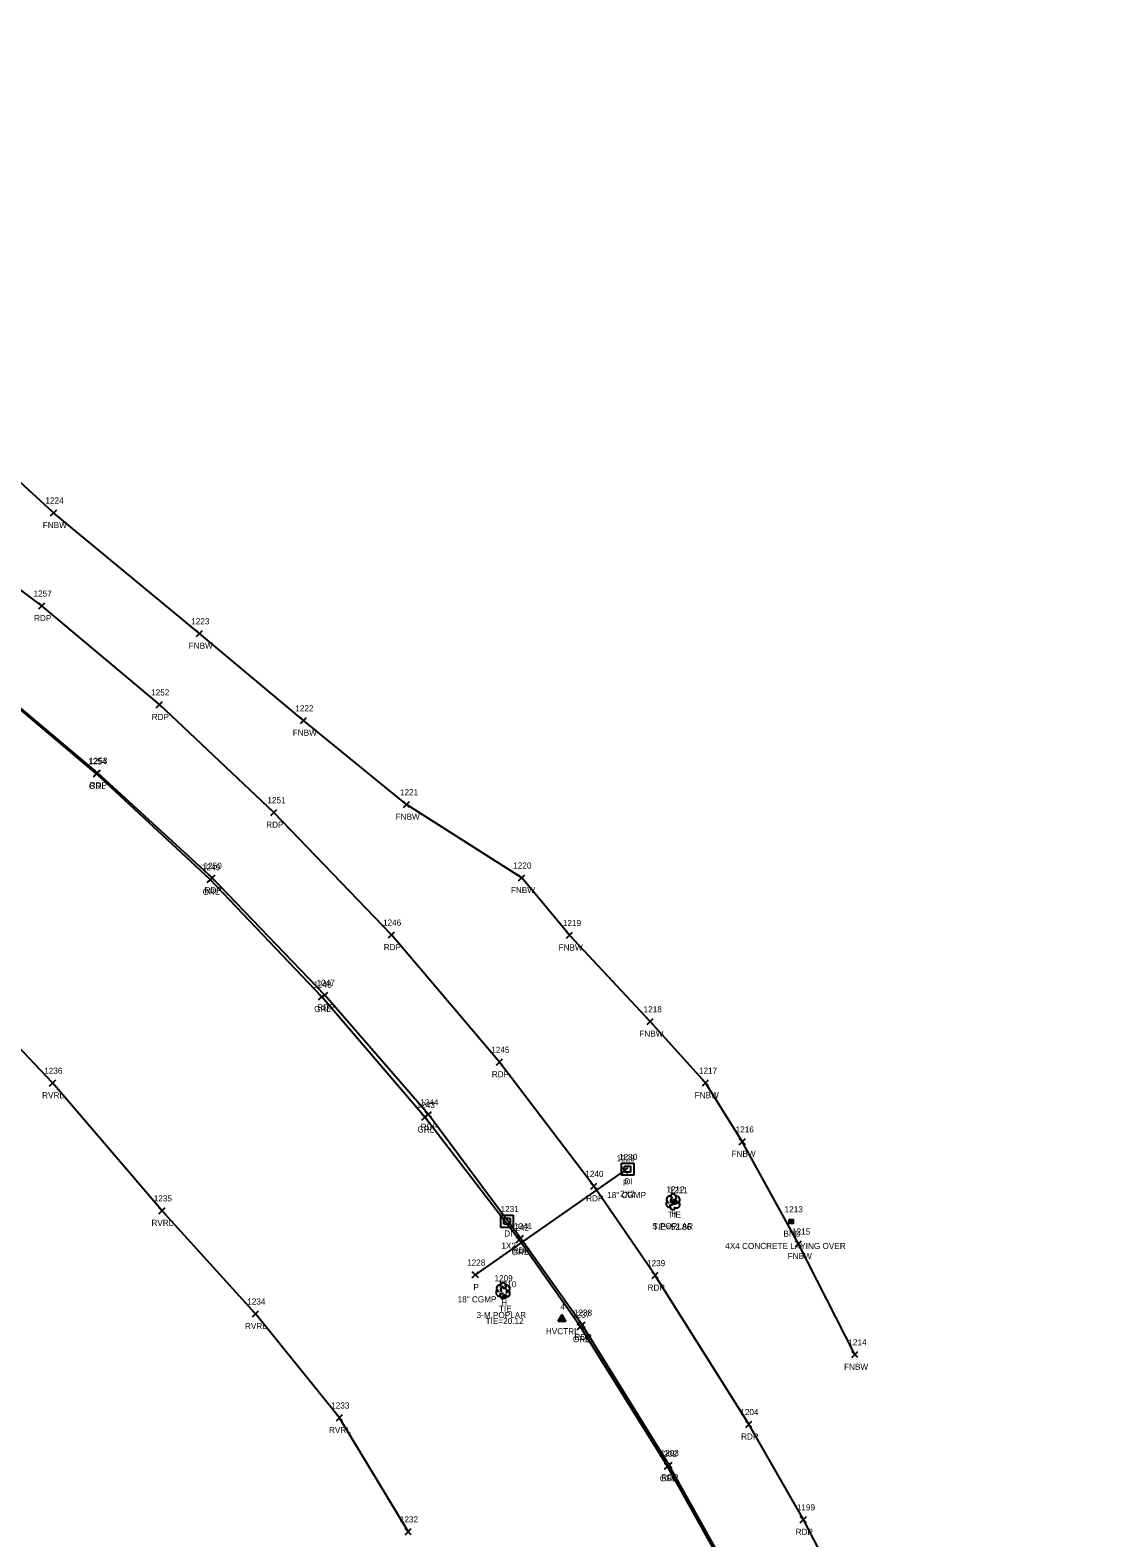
# Model space of a CAD drawing. Extents: x 1503463 to 1505240, y 712171 to 717196.
# Drawn here: x 1504304.4 to 1504657.1, y 714854.3 to 715346.9 of the extents above; entities that cross this region are included whole.
import ezdxf

# ---------------------------------------------------------------- set-up
doc = ezdxf.new("R2010")
doc.units = 0
for name, color, linetype in [('C_A', 7, 'Continuous'), ('C_C', 7, 'Continuous'), ('C_I', 7, 'Continuous'), ('CBP', 7, 'Continuous'), ('CPSM', 7, 'Continuous'), ('D_A', 7, 'Continuous'), ('D_C', 7, 'Continuous'), ('D_I', 7, 'Continuous'), ('D_TIC', 7, 'Continuous'), ('DCP', 7, 'Continuous'), ('DS', 7, 'Continuous'), ('L_A', 7, 'Continuous'), ('L_C', 7, 'Continuous'), ('L_I', 7, 'Continuous'), ('L_TIC', 7, 'Continuous'), ('LAWE', 7, 'Continuous'), ('LFNC', 7, 'Continuous'), ('LTD', 7, 'Continuous'), ('M_A', 7, 'Continuous'), ('M_C', 7, 'Continuous'), ('M_I', 7, 'Continuous'), ('MHBP', 7, 'Continuous'), ('P_A', 7, 'Continuous'), ('P_I', 7, 'Continuous'), ('P_TIC', 7, 'Continuous'), ('PET', 7, 'Continuous'), ('R_A', 7, 'Continuous'), ('R_I', 7, 'Continuous'), ('R_TIC', 7, 'Continuous'), ('RGR', 7, 'Continuous')]:
    doc.layers.add(name, color=color, linetype=linetype)

msp = doc.modelspace()

# ---------------------------------------------------------------- linework, layer by layer
at = {"layer": 'CBP'}
for centre, radius in [((1504515, 714963.91), 0.625), ((1504515, 714963.91), 0.0833), ((1504459.64, 714933.16), 0.625), ((1504459.64, 714933.16), 0.0833)]:
    msp.add_circle(centre, radius, dxfattribs=at)
at = {"layer": 'CPSM'}
for p, q in [((1504477.12, 714925.07), (1504478.37, 714927.24)), ((1504479.62, 714925.07), (1504478.37, 714927.24)), ((1504478.37, 714925.8), (1504478.37, 714927.24)), ((1504477.12, 714925.07), (1504478.37, 714925.8)), ((1504477.12, 714925.07), (1504479.62, 714925.07)), ((1504478.37, 714925.8), (1504478.37, 714925.8)), ((1504478.37, 714925.8), (1504479.62, 714925.07))]:
    msp.add_line(p, q, dxfattribs=at)
at = {"layer": 'D_TIC'}
for points in [[(1504497.89, 714973.3), (1504499.89, 714975.3)], [(1504499.89, 714973.3), (1504497.89, 714975.3)], [(1504448.99, 714939.23), (1504450.99, 714941.23)], [(1504450.99, 714939.23), (1504448.99, 714941.23)]]:
    msp.add_lwpolyline(points, dxfattribs=at)
at = {"layer": 'DCP'}
msp.add_lwpolyline([(1504449.99, 714940.23), (1504498.89, 714974.3)], dxfattribs=at)
at = {"layer": 'DS'}
for p, q in [((1504497.76, 714976.75), (1504501.76, 714976.75)), ((1504497.76, 714972.75), (1504497.76, 714976.75)), ((1504498.76, 714973.75), (1504498.76, 714975.75)), ((1504498.76, 714975.75), (1504500.76, 714975.75)), ((1504500.76, 714975.75), (1504500.76, 714973.75)), ((1504501.76, 714976.75), (1504501.76, 714972.75)), ((1504501.76, 714972.75), (1504497.76, 714972.75)), ((1504500.76, 714973.75), (1504498.76, 714973.75)), ((1504499.77, 714974.75), (1504499.77, 714974.75)), ((1504499.77, 714974.75), (1504499.77, 714974.75)), ((1504458.36, 714959.73), (1504462.36, 714959.73)), ((1504458.36, 714955.73), (1504458.36, 714959.73)), ((1504462.36, 714955.73), (1504458.36, 714955.73)), ((1504459.36, 714956.73), (1504459.36, 714958.73)), ((1504459.36, 714958.73), (1504461.36, 714958.73)), ((1504461.36, 714956.73), (1504459.36, 714956.73)), ((1504460.37, 714957.74), (1504460.37, 714957.74)), ((1504460.37, 714957.74), (1504460.37, 714957.74)), ((1504461.36, 714958.73), (1504461.36, 714956.73)), ((1504462.36, 714959.73), (1504462.36, 714955.73))]:
    msp.add_line(p, q, dxfattribs=at)
at = {"layer": 'L_TIC'}
for points in [[(1504311.1, 715188.24), (1504313.1, 715190.24)], [(1504313.1, 715188.24), (1504311.1, 715190.24)], [(1504358.79, 715148.8), (1504360.79, 715150.8)], [(1504360.79, 715148.8), (1504358.79, 715150.8)], [(1504392.83, 715120.36), (1504394.83, 715122.36)], [(1504394.83, 715120.36), (1504392.83, 715122.36)], [(1504426.46, 715092.92), (1504428.46, 715094.92)], [(1504428.46, 715092.92), (1504426.46, 715094.92)], [(1504464.15, 715068.97), (1504466.15, 715070.97)], [(1504466.15, 715068.97), (1504464.15, 715070.97)], [(1504479.75, 715050.19), (1504481.75, 715052.19)], [(1504481.75, 715050.19), (1504479.75, 715052.19)], [(1504506.14, 715022.01), (1504508.14, 715024.01)], [(1504508.14, 715022.01), (1504506.14, 715024.01)], [(1504310.78, 715001.92), (1504312.78, 715003.92)], [(1504312.78, 715001.92), (1504310.78, 715003.92)], [(1504524.24, 715001.94), (1504526.24, 715003.94)], [(1504526.24, 715001.94), (1504524.24, 715003.94)], [(1504536.29, 714982.75), (1504538.29, 714984.75)], [(1504538.29, 714982.75), (1504536.29, 714984.75)], [(1504346.53, 714960.21), (1504348.53, 714962.21)], [(1504348.53, 714960.21), (1504346.53, 714962.21)], [(1504554.66, 714949.38), (1504556.66, 714951.38)], [(1504556.66, 714949.38), (1504554.66, 714951.38)], [(1504377.11, 714926.51), (1504379.11, 714928.51)], [(1504379.11, 714926.51), (1504377.11, 714928.51)], [(1504573.09, 714913.16), (1504575.09, 714915.16)], [(1504575.09, 714913.16), (1504573.09, 714915.16)], [(1504404.57, 714892.54), (1504406.57, 714894.54)], [(1504406.57, 714892.54), (1504404.57, 714894.54)], [(1504427.01, 714855.32), (1504429.01, 714857.32)], [(1504429.01, 714855.32), (1504427.01, 714857.32)]]:
    msp.add_lwpolyline(points, dxfattribs=at)
at = {"layer": 'LAWE'}
msp.add_lwpolyline([(1504428.01, 714856.32), (1504405.57, 714893.54), (1504378.11, 714927.51), (1504347.53, 714961.21), (1504311.78, 715002.92), (1504271.16, 715045.67), (1504223.13, 715076), (1504189.07, 715094.24), (1504152.61, 715106.17), (1504141.48, 715110.8), (1504128.72, 715116.26)], dxfattribs=at)
at = {"layer": 'LFNC'}
msp.add_lwpolyline([(1504574.09, 714914.16), (1504555.66, 714950.38), (1504537.29, 714983.75), (1504525.24, 715002.94), (1504507.14, 715023.01), (1504480.75, 715051.19), (1504465.15, 715069.97), (1504427.46, 715093.92), (1504393.83, 715121.36), (1504359.79, 715149.8), (1504312.1, 715189.24), (1504289.94, 715209.45), (1504272.51, 715223.61)], dxfattribs=at)
at = {"layer": 'LTD'}
for p, q in [((1504514.6, 714964.13), (1504514.6, 714964.13)), ((1504514.6, 714964.13), (1504514.6, 714964.13)), ((1504459.02, 714935.1), (1504459.02, 714935.1)), ((1504459.02, 714935.1), (1504459.02, 714935.1))]:
    msp.add_line(p, q, dxfattribs=at)
for centre in [(1504514.65, 714965.57), (1504459.07, 714936.54)]:
    msp.add_arc(centre, 1.05, 335.5272, 180.9563, dxfattribs=at)
for centre, major_axis, ratio, start_param, end_param in [((1504513.81, 714964.8), (1.21, -0.51), 0.895232, 1.570796, 4.712389), ((1504515.64, 714964.72), (-1.14, -0.48), 0.949671, 1.570796, 4.712389), ((1504513.52, 714963.42), (0.58, -1.04), 0.959034, 3.141593, 6.283185), ((1504514.6, 714962.63), (0.26, 1.06), 0.942809, 1.570796, 4.712389), ((1504514.14, 714963.38), (-0.625, -0.083), 0.423636, 0, 3.141593), ((1504514.39, 714964.59), (-0.208, -0.792), 0.645439, 3.141593, 6.283185), ((1504515.1, 714963.97), (-0.5, 0.667), 0.989748, 3.141593, 6.283185), ((1504515.6, 714963.3), (-1.09, 0.79), 0.841452, 1.570796, 4.712389), ((1504458.23, 714935.77), (1.21, -0.51), 0.895232, 1.570796, 4.712389), ((1504458.82, 714935.56), (-0.208, -0.792), 0.645439, 3.141593, 6.283185), ((1504460.07, 714935.69), (-1.14, -0.48), 0.949671, 1.570796, 4.712389), ((1504457.94, 714934.39), (0.58, -1.04), 0.959034, 3.141593, 6.283185), ((1504459.02, 714933.6), (0.26, 1.06), 0.942809, 1.570796, 4.712389), ((1504458.57, 714934.35), (-0.625, -0.083), 0.423636, 0, 3.141593), ((1504459.52, 714934.94), (-0.5, 0.667), 0.989748, 3.141593, 6.283185), ((1504460.02, 714934.27), (-1.09, 0.79), 0.841452, 1.570796, 4.712389)]:
    msp.add_ellipse(centre, major_axis=major_axis, ratio=ratio, start_param=start_param, end_param=end_param, dxfattribs=at)
at = {"layer": 'MHBP'}
msp.add_lwpolyline([(1504552.62, 714958.28), (1504553.87, 714958.28), (1504553.87, 714957.03), (1504552.62, 714957.03)], close=True, dxfattribs=at)
msp.add_circle((1504553.25, 714957.66), 0.0833, dxfattribs=at)
at = {"layer": 'P_TIC'}
for points in [[(1504307.22, 715157.84), (1504309.22, 715159.84)], [(1504309.22, 715157.84), (1504307.22, 715159.84)], [(1504345.68, 715125.54), (1504347.68, 715127.54)], [(1504347.68, 715125.54), (1504345.68, 715127.54)], [(1504325.41, 715103.24), (1504327.41, 715105.24)], [(1504327.41, 715103.24), (1504325.41, 715105.24)], [(1504383.13, 715090.33), (1504385.13, 715092.33)], [(1504385.13, 715090.33), (1504383.13, 715092.33)], [(1504362.93, 715068.91), (1504364.93, 715070.91)], [(1504364.93, 715068.91), (1504362.93, 715070.91)], [(1504421.56, 715050.33), (1504423.56, 715052.33)], [(1504423.56, 715050.33), (1504421.56, 715052.33)], [(1504399.79, 715030.63), (1504401.79, 715032.63)], [(1504401.79, 715030.63), (1504399.79, 715032.63)], [(1504456.88, 715008.77), (1504458.88, 715010.77)], [(1504458.88, 715008.77), (1504456.88, 715010.77)], [(1504433.64, 714991.6), (1504435.64, 714993.6)], [(1504435.64, 714991.6), (1504433.64, 714993.6)], [(1504487.73, 714968.22), (1504489.73, 714970.22)], [(1504489.73, 714968.22), (1504487.73, 714970.22)], [(1504463.76, 714951.16), (1504465.76, 714953.16)], [(1504465.76, 714951.16), (1504463.76, 714953.16)], [(1504507.82, 714939.05), (1504509.82, 714941.05)], [(1504509.82, 714939.05), (1504507.82, 714941.05)], [(1504483.92, 714922.88), (1504485.92, 714924.88)], [(1504485.92, 714922.88), (1504483.92, 714924.88)], [(1504538.4, 714890.39), (1504540.4, 714892.39)], [(1504540.4, 714890.39), (1504538.4, 714892.39)], [(1504512.33, 714877.02), (1504514.33, 714879.02)], [(1504514.33, 714877.02), (1504512.33, 714879.02)], [(1504556.24, 714859.24), (1504558.24, 714861.24)], [(1504558.24, 714859.24), (1504556.24, 714861.24)]]:
    msp.add_lwpolyline(points, dxfattribs=at)
at = {"layer": 'PET'}
for points in [[(1504628.86, 714571.69), (1504621.33, 714603.22), (1504611.21, 714644.87), (1504597.35, 714691.39), (1504582.78, 714732.74), (1504571.53, 714760.83), (1504551.13, 714806.83), (1504531.24, 714845.96), (1504513.33, 714878.02), (1504484.92, 714923.88), (1504464.76, 714952.16), (1504434.64, 714992.6), (1504400.79, 715031.63), (1504363.93, 715069.91), (1504326.41, 715104.24), (1504288.97, 715135.69), (1504248.31, 715166.3), (1504201.61, 715200.45), (1504154.53, 715234.59), (1504120.68, 715258.8), (1504069.42, 715296.54), (1504012.71, 715338.31), (1504010.26, 715341.79), (1503951.37, 715387.03)], [(1504657.14, 714577.6), (1504649.31, 714613.48), (1504639.83, 714651.58), (1504624, 714703.83), (1504610.47, 714743.63), (1504599.62, 714771.44), (1504577.65, 714820.8), (1504557.24, 714860.24), (1504539.4, 714891.39), (1504508.82, 714940.05), (1504488.73, 714969.22), (1504457.88, 715009.77), (1504422.56, 715051.33), (1504384.13, 715091.33), (1504346.68, 715126.54), (1504308.22, 715158.84), (1504264.39, 715191.56), (1504218.27, 715225.33), (1504171.61, 715259.82), (1504137.77, 715284.36), (1504086.6, 715320.97), (1504048.23, 715348.08)]]:
    msp.add_lwpolyline(points, dxfattribs=at)
at = {"layer": 'R_TIC'}
for points in [[(1504325.1, 715102.99), (1504327.1, 715104.99)], [(1504327.1, 715102.99), (1504325.1, 715104.99)], [(1504362.28, 715068.4), (1504364.28, 715070.4)], [(1504364.28, 715068.4), (1504362.28, 715070.4)], [(1504398.75, 715030.08), (1504400.75, 715032.08)], [(1504400.75, 715030.08), (1504398.75, 715032.08)], [(1504432.51, 714990.73), (1504434.51, 714992.73)], [(1504434.51, 714990.73), (1504432.51, 714992.73)], [(1504463.3, 714950.66), (1504465.3, 714952.66)], [(1504465.3, 714950.66), (1504463.3, 714952.66)], [(1504483.33, 714922.22), (1504485.33, 714924.22)], [(1504485.33, 714922.22), (1504483.33, 714924.22)], [(1504511.79, 714876.73), (1504513.79, 714878.73)], [(1504513.79, 714876.73), (1504511.79, 714878.73)]]:
    msp.add_lwpolyline(points, dxfattribs=at)
at = {"layer": 'RGR'}
msp.add_lwpolyline([(1504616.71, 714600.2), (1504618.77, 714605.75), (1504618.48, 714611.67), (1504610.41, 714644.61), (1504596.35, 714690.53), (1504582.15, 714732.64), (1504570.9, 714760.4), (1504550.39, 714806.66), (1504530.74, 714845.7), (1504512.79, 714877.73), (1504484.33, 714923.22), (1504464.3, 714951.66), (1504433.51, 714991.73), (1504399.75, 715031.08), (1504363.28, 715069.4), (1504326.1, 715103.99), (1504288.79, 715135.46), (1504248.14, 715165.9), (1504201.6, 715200.12), (1504153.7, 715233.3), (1504118.14, 715255.35), (1504061.18, 715288.67)], dxfattribs=at)

# ---------------------------------------------------------------- texts
at = {"layer": 'C_A'}
for s, p in [('TIE', (1504513.08, 714958.91)), ('TIE', (1504457.72, 714928.16)), ('HVCTRL', (1504473.07, 714920.8))]:
    msp.add_text(s, height=2, dxfattribs=at).set_placement(p)
at = {"layer": 'C_C'}
for s, p in [('TIE=52.86', (1504508.17, 714954.91)), ('TIE=20.12', (1504453.36, 714924.16))]:
    msp.add_text(s, height=2, dxfattribs=at).set_placement(p)
at = {"layer": 'C_I'}
for s, p in [('1211', (1504513.44, 714966.91)), ('1210', (1504457.43, 714936.16)), ('4', (1504477.81, 714928.8))]:
    msp.add_text(s, height=2, dxfattribs=at).set_placement(p)
at = {"layer": 'D_A'}
for s, p in [('P', (1504498.26, 714969.3)), ('DI', (1504498.82, 714969.75)), ('DI', (1504459.42, 714952.74)), ('P', (1504449.37, 714935.23))]:
    msp.add_text(s, height=2, dxfattribs=at).set_placement(p)
at = {"layer": 'D_C'}
for s, p in [('18" CGMP', (1504493.1, 714965.3)), ('2X2', (1504497.34, 714965.75)), ('1X2', (1504458.51, 714948.74)), ('18" CGMP', (1504444.2, 714931.23))]:
    msp.add_text(s, height=2, dxfattribs=at).set_placement(p)
at = {"layer": 'D_I'}
for s, p in [('1229', (1504496.19, 714977.3)), ('1230', (1504496.99, 714977.75)), ('1231', (1504458.24, 714960.74)), ('1228', (1504447.3, 714943.23))]:
    msp.add_text(s, height=2, dxfattribs=at).set_placement(p)
at = {"layer": 'L_A'}
for s, p in [('FNBW', (1504308.57, 715184.24)), ('FNBW', (1504356.26, 715144.8)), ('FNBW', (1504390.3, 715116.36)), ('FNBW', (1504423.94, 715088.92)), ('FNBW', (1504461.62, 715064.97)), ('FNBW', (1504477.22, 715046.19)), ('FNBW', (1504503.61, 715018.01)), ('RVRL', (1504308.35, 714997.92)), ('FNBW', (1504521.71, 714997.94)), ('FNBW', (1504533.76, 714978.75)), ('H', (1504514.03, 714959.13)), ('RVRL', (1504344.09, 714956.21)), ('FNBW', (1504552.13, 714945.38)), ('H', (1504458.46, 714930.1)), ('RVRL', (1504374.68, 714922.51)), ('FNBW', (1504570.56, 714909.16)), ('RVRL', (1504402.14, 714888.54))]:
    msp.add_text(s, height=2, dxfattribs=at).set_placement(p)
at = {"layer": 'L_C'}
for s, p in [('S.POPLAR', (1504507.81, 714955.13)), ('3-M.POPLAR', (1504450.39, 714926.1))]:
    msp.add_text(s, height=2, dxfattribs=at).set_placement(p)
at = {"layer": 'L_I'}
for s, p in [('1224', (1504309.41, 715192.24)), ('1223', (1504357.09, 715152.8)), ('1222', (1504391.13, 715124.36)), ('1221', (1504425.34, 715096.92)), ('1220', (1504462.37, 715072.97)), ('1219', (1504478.61, 715054.19)), ('1218', (1504505.02, 715026.01)), ('1236', (1504309.03, 715005.92)), ('1217', (1504523.11, 715005.94)), ('1216', (1504535.11, 714986.75)), ('1235', (1504344.83, 714964.21)), ('1212', (1504512.47, 714967.13)), ('1215', (1504553.53, 714953.38)), ('1209', (1504456.25, 714938.1)), ('1234', (1504375.42, 714930.51)), ('1214', (1504571.96, 714917.16)), ('1233', (1504402.88, 714896.54)), ('1232', (1504425.31, 714859.32))]:
    msp.add_text(s, height=2, dxfattribs=at).set_placement(p)
at = {"layer": 'M_A'}
msp.add_text('BND', height=2, dxfattribs=at).set_placement((1504550.73, 714952.66))
at = {"layer": 'M_C'}
msp.add_text('4X4 CONCRETE LAYING OVER', height=2, dxfattribs=at).set_placement((1504531.7, 714948.66))
at = {"layer": 'M_I'}
msp.add_text('1213', height=2, dxfattribs=at).set_placement((1504551.12, 714960.66))
at = {"layer": 'P_A'}
for p in [(1504305.7, 715153.84), (1504344.17, 715121.54), (1504323.9, 715099.24), (1504381.61, 715086.33), (1504361.42, 715064.91), (1504420.05, 715046.33), (1504398.28, 715026.63), (1504455.37, 715004.77), (1504432.12, 714987.6), (1504486.22, 714964.22), (1504462.25, 714947.16), (1504506.31, 714935.05), (1504482.4, 714918.88), (1504536.89, 714886.39), (1504510.81, 714873.02), (1504554.73, 714855.24)]:
    msp.add_text('RDP', height=2, dxfattribs=at).set_placement(p)
at = {"layer": 'P_I'}
for s, p in [('1257', (1504305.52, 715161.84)), ('1252', (1504343.99, 715129.54)), ('1253', (1504323.72, 715107.24)), ('1251', (1504382, 715094.33)), ('1250', (1504361.15, 715072.91)), ('1246', (1504419.82, 715054.33)), ('1247', (1504398.1, 715034.63)), ('1245', (1504455.19, 715012.77)), ('1244', (1504431.94, 714995.6)), ('1240', (1504485.95, 714972.22)), ('1241', (1504462.63, 714955.16)), ('1239', (1504506.12, 714943.05)), ('1238', (1504482.22, 714926.88)), ('1204', (1504536.63, 714894.39)), ('1203', (1504510.55, 714881.02)), ('1199', (1504555.11, 714863.24))]:
    msp.add_text(s, height=2, dxfattribs=at).set_placement(p)
at = {"layer": 'R_A'}
for p in [(1504323.64, 715098.99), (1504360.82, 715064.4), (1504397.29, 715026.08), (1504431.05, 714986.73), (1504461.84, 714946.66), (1504481.88, 714918.22), (1504510.33, 714872.73)]:
    msp.add_text('GRL', height=2, dxfattribs=at).set_placement(p)
at = {"layer": 'R_I'}
for s, p in [('1254', (1504323.41, 715106.99)), ('1249', (1504360.58, 715072.4)), ('1248', (1504397.06, 715034.08)), ('1243', (1504430.81, 714994.73)), ('1242', (1504461.6, 714954.66)), ('1237', (1504481.64, 714926.22)), ('1202', (1504510.02, 714880.73))]:
    msp.add_text(s, height=2, dxfattribs=at).set_placement(p)

doc.saveas('drawing.dxf')
